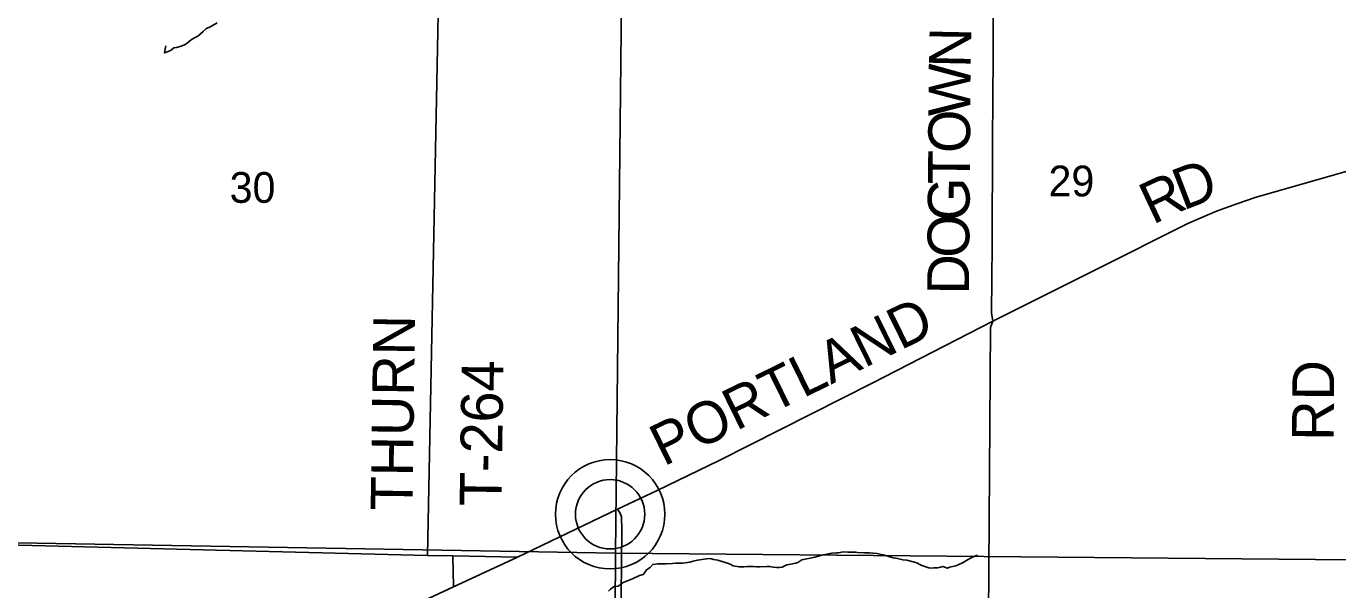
# Model space of a CAD drawing. Extents: x -8.5 to 18.7, y -20.3 to 7.
# Drawn here: x 11.845 to 15.411, y -8.949 to -7.416 of the extents above; entities that cross this region are included whole.
import ezdxf

# ---------------------------------------------------------------- set-up
doc = ezdxf.new("R2010")
doc.units = 0
for name, color, linetype in [('GM_X_County_Road', 7, 'Continuous'), ('GM_X_County_Road_Text', 7, 'Continuous'), ('GM_X_Minor_River', 7, 'Continuous'), ('GM_X_Section', 7, 'Continuous'), ('GM_X_Section_Text', 7, 'Continuous'), ('GM_X_Township_Road', 7, 'Continuous'), ('GM_X_Township_Road_Text', 7, 'Continuous'), ('GM_X_Unincorporated', 7, 'Continuous'), ('GM_X_Unincorporated_Location', 7, 'Continuous')]:
    doc.layers.add(name, color=color, linetype=linetype)

msp = doc.modelspace()

# ---------------------------------------------------------------- linework, layer by layer
at = {"layer": 'GM_X_County_Road'}
for points in [[(14.4736, -8.218), (14.7523, -8.0784), (15.0039, -7.9529), (15.0371, -7.9379), (15.0816, -7.9192), (15.14, -7.8978), (15.1868, -7.882), (15.469, -7.8012), (15.7777, -7.7167), (16.1216, -7.621), (16.4603, -7.5284), (16.6028, -7.4859), (16.7559, -7.4377), (16.8934, -7.4072), (17.0345, -7.3824), (17.4857, -7.308), (17.7182, -7.2669), (18.0794, -7.208), (18.5689, -7.1263)], [(11.4546, -9.6627), (12.4441, -9.2033), (13.0064, -8.9417), (13.1807, -8.8606), (13.4526, -8.7299), (13.5606, -8.6794), (13.7291, -8.5973), (14.1473, -8.386), (14.4736, -8.218)]]:
    msp.add_lwpolyline(points, dxfattribs=at)
at = {"layer": 'GM_X_Minor_River'}
for points in [[(12.3643, -7.4063), (12.3469, -7.4163), (12.3333, -7.4232), (12.3257, -7.43), (12.3114, -7.443), (12.3008, -7.4484), (12.2939, -7.453), (12.2886, -7.4568), (12.2826, -7.4614), (12.275, -7.4667), (12.2637, -7.4706), (12.2538, -7.4737), (12.2462, -7.4745), (12.2387, -7.4806), (12.2311, -7.4844), (12.2212, -7.4883), (12.2249, -7.4693)], [(13.4284, -8.953), (13.4337, -8.9477), (13.4437, -8.9402), (13.4543, -8.9396), (13.4604, -8.9358), (13.4665, -8.9306), (13.4931, -8.9194), (13.5129, -8.9105), (13.5221, -8.9075), (13.5282, -8.9007), (13.532, -8.8954), (13.5412, -8.8887), (13.5488, -8.8804), (13.5625, -8.879), (13.5708, -8.8791), (13.5761, -8.8784), (13.5853, -8.8784), (13.6019, -8.8778), (13.611, -8.8772), (13.6247, -8.8773), (13.63, -8.8766), (13.649, -8.8737), (13.6589, -8.8715), (13.6703, -8.8686), (13.6946, -8.865), (13.7029, -8.8643), (13.7082, -8.8651), (13.7135, -8.8667), (13.7256, -8.8691), (13.7453, -8.8753), (13.7544, -8.8777), (13.7612, -8.8808), (13.7672, -8.8838), (13.7839, -8.887), (13.796, -8.8871), (13.8059, -8.8857), (13.8226, -8.8859), (13.8317, -8.8867), (13.8385, -8.8868), (13.859, -8.8862), (13.8673, -8.8863)], [(13.8673, -8.8863), (13.8764, -8.8879), (13.8855, -8.8887), (13.8923, -8.8888), (13.9007, -8.8881), (13.9136, -8.8813), (13.9243, -8.8792), (13.9379, -8.877), (13.9433, -8.8755), (13.9539, -8.868), (13.9767, -8.8629), (13.9897, -8.8608), (14.0056, -8.8556), (14.0125, -8.8541), (14.0261, -8.8512), (14.036, -8.8498), (14.0482, -8.8491), (14.0535, -8.8484), (14.0664, -8.8462), (14.0793, -8.8471), (14.1005, -8.8473), (14.1058, -8.8481), (14.124, -8.8483), (14.1376, -8.8492), (14.1581, -8.8509), (14.1755, -8.854), (14.1846, -8.8572), (14.1907, -8.8587), (14.196, -8.8603), (14.202, -8.8626), (14.2088, -8.8634), (14.2141, -8.8643), (14.2285, -8.8674), (14.2391, -8.8683), (14.2603, -8.8745), (14.2664, -8.8761), (14.2732, -8.88), (14.2784, -8.8823), (14.286, -8.8854), (14.2913, -8.887), (14.2989, -8.8893), (14.3064, -8.8901), (14.3125, -8.8894), (14.3239, -8.8895), (14.3307, -8.8881), (14.3376, -8.8859), (14.3451, -8.889), (14.3504, -8.8905), (14.3558, -8.8875), (14.3725, -8.8839), (14.3808, -8.8809), (14.393, -8.8749), (14.4045, -8.8675), (14.4144, -8.8622), (14.4266, -8.857), (14.4319, -8.8548)]]:
    msp.add_lwpolyline(points, dxfattribs=at)
at = {"layer": 'GM_X_Section'}
for points in [[(13.4691, -6.8424), (13.4473, -8.8495), (11.4531, -8.8156), (11.4833, -6.7972)], [(13.4691, -6.8424), (15.4709, -6.8673), (15.4513, -8.8676), (13.4473, -8.8495)], [(11.4531, -8.8156), (13.4473, -8.8495), (13.4352, -10.8471), (11.4305, -10.8167)]]:
    msp.add_lwpolyline(points, close=True, dxfattribs=at)
at = {"layer": 'GM_X_Township_Road'}
msp.add_line((13.005, -8.8573), (13.0064, -8.9417), dxfattribs=at)
for points in [[(12.9365, -8.856), (12.9887, -6.1861), (12.9958, -5.7774), (12.9993, -5.458), (13, -5.233), (13.002, -5.0003), (13.0032, -4.8475), (13.002, -4.8237)], [(14.4736, -8.218), (14.4695, -8.1961), (14.4715, -8.0107), (14.4729, -7.7268), (14.4739, -7.498), (14.4746, -7.3799)], [(14.4489, -10.858), (14.4674, -8.2358), (14.4736, -8.218)], [(13.4579, -10.8439), (13.4585, -9.4012), (13.462, -9.0532), (13.4642, -8.7866), (13.4636, -8.7506), (13.4597, -8.7407), (13.4526, -8.7299)], [(11.465, -8.8192), (12.9365, -8.856), (13.005, -8.8573), (13.1807, -8.8606)]]:
    msp.add_lwpolyline(points, dxfattribs=at)
at = {"layer": 'GM_X_Unincorporated'}
for radius in [0.1488, 0.0943]:
    msp.add_circle((13.4327, -8.7438), radius, dxfattribs=at)
at = {"layer": 'GM_X_Unincorporated_Location'}
msp.add_line((13.4327, -8.7438), (13.4327, -8.7438), dxfattribs=at)

# ---------------------------------------------------------------- texts
at = {"layer": 'GM_X_County_Road_Text'}
for s, height, rotation, p in [('D', 0.1136, 20.9193, (14.9905, -7.9178)), ('R', 0.1136, 25.1371, (14.908, -7.9566)), ('PORTLAND', 0.11364, 26.1616, (13.5784, -8.6147))]:
    msp.add_text(s, height=height, rotation=rotation, dxfattribs=at).set_placement(p)
at = {"layer": 'GM_X_Section_Text'}
for s, p in [('29', (14.6248, -7.8788)), ('30', (12.3981, -7.8963))]:
    msp.add_text(s, height=0.08371, rotation=0, dxfattribs=at).set_placement(p)
at = {"layer": 'GM_X_Township_Road_Text'}
for s, height, rotation, p in [('N', 0.1136, 88.8124, (14.4129, -7.5299)), ('W', 0.1136, 89.5712, (14.4119, -7.6611)), ('O', 0.1136, 89.5861, (14.4112, -7.7611)), ('T', 0.1136, 89.58, (14.4106, -7.8461)), ('G', 0.1136, 89.5851, (14.4099, -7.9461)), ('O', 0.1136, 89.5811, (14.4091, -8.0461)), ('D', 0.1136, 89.5847, (14.4084, -8.1461)), ('THURN', 0.11364, 89.2019, (12.8951, -8.7342)), ('T-264', 0.11364, 89.1579, (13.137, -8.7227)), ('RD', 0.11364, 89.5063, (15.4001, -8.5444))]:
    msp.add_text(s, height=height, rotation=rotation, dxfattribs=at).set_placement(p)

doc.saveas('drawing.dxf')
